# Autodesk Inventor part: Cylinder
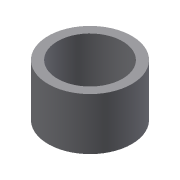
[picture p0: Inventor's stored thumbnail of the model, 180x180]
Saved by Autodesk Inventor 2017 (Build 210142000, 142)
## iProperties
Created: 2010-05
Part Number: Cylinder
Document SubType Name: Modeling
Designer: CADSoft
Density: 1 g/cm^3
Material: Generic
Appearance: Default
Author: CADSoft
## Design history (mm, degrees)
sketch "Sketch1"
  geometry: C1 r 87.5 at (0, 0); C2 r 112.5 at (0, 0); 1 further point
  constraints: 2 centre point, 2 coincident
  dimensions: "d0" = 175 diameter of C1; "d1" = 225 diameter of C2
extrude "Extrusion1" new body sketch "Sketch1" distance "d2" = 140; taper "d3" = 0 deg
body "Solid1"
